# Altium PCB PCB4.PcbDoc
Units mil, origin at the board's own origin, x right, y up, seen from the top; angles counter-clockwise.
Board outline 3880 x 2525 mil, 2 copper layers (Top Layer, Bottom Layer); 34 components, 40 nets, 108 pads, 1 vias.
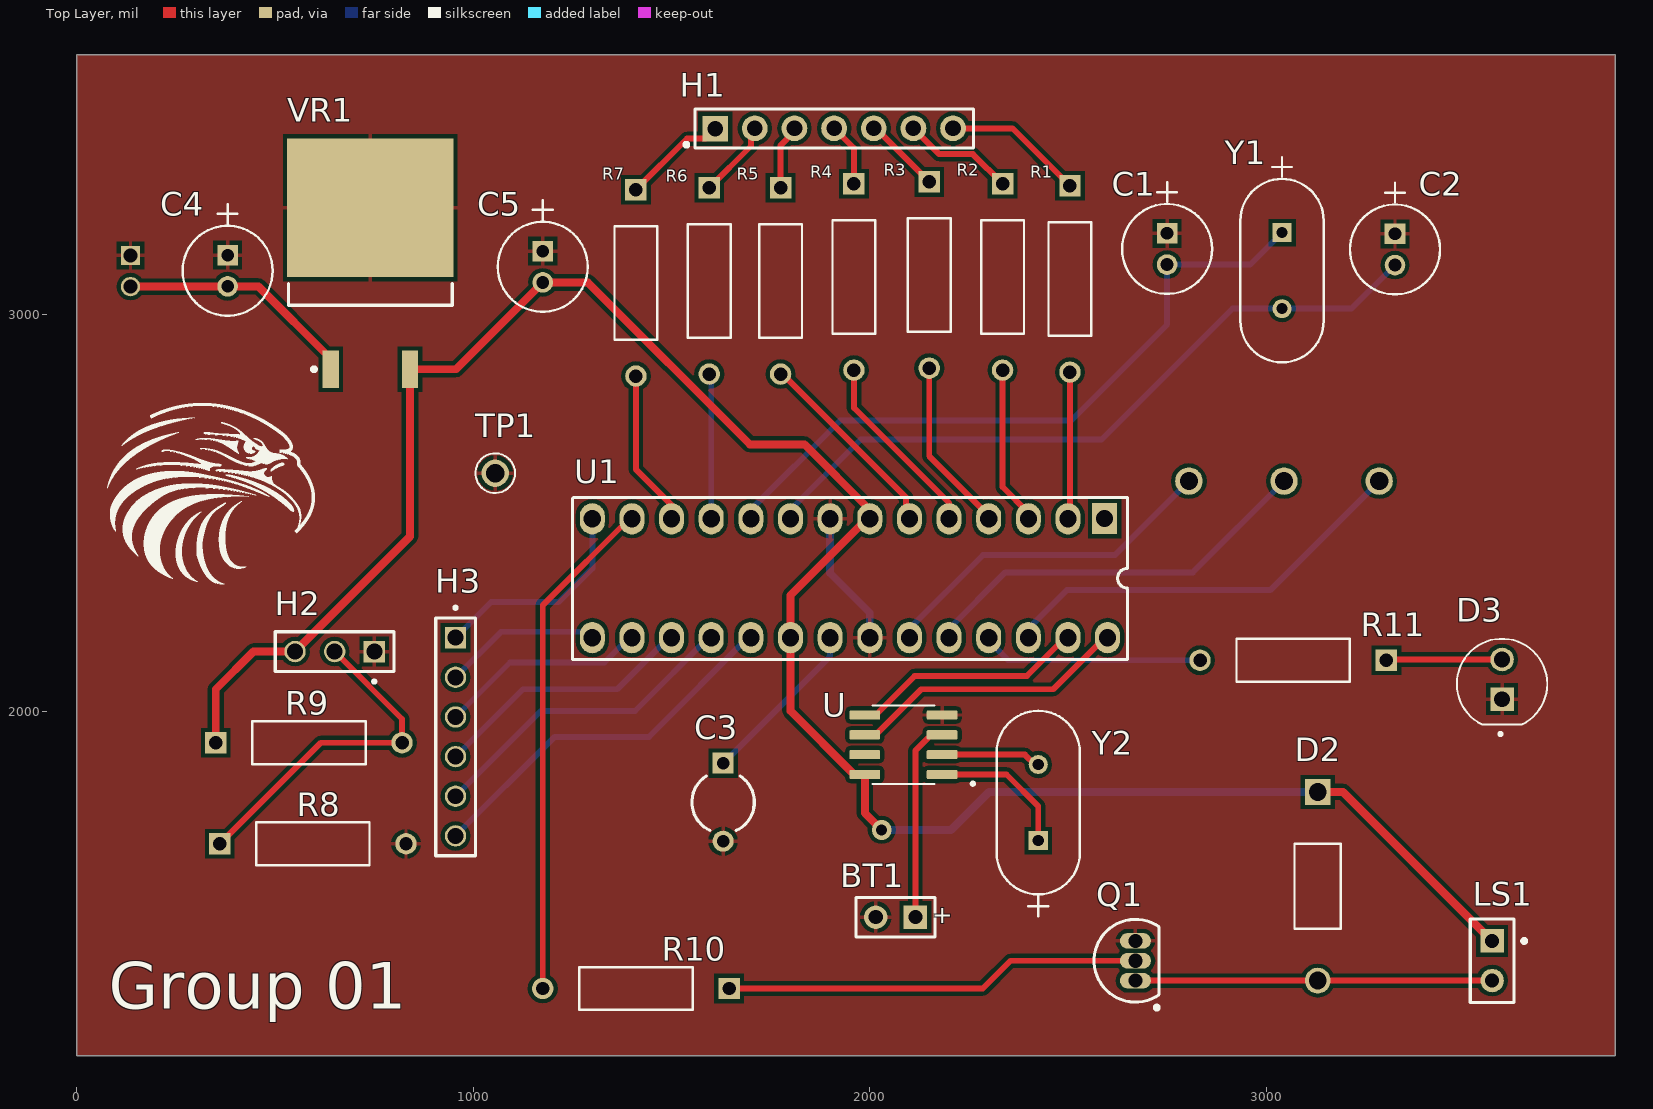
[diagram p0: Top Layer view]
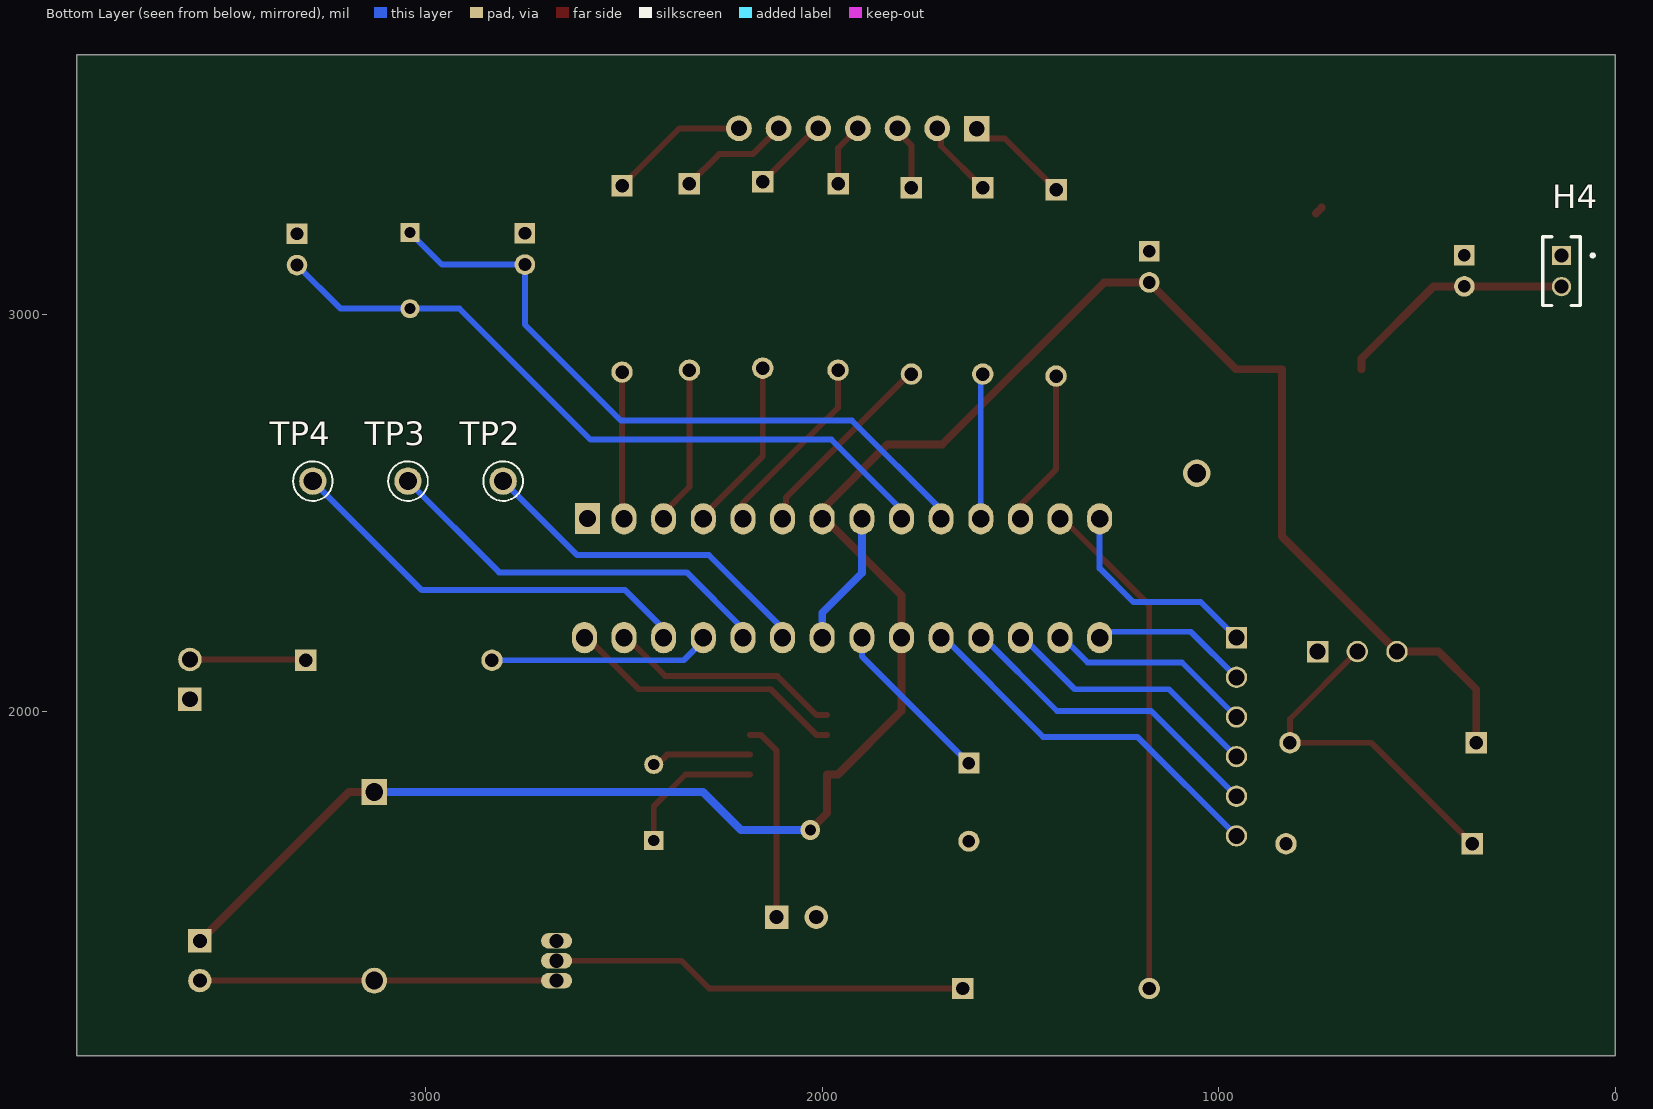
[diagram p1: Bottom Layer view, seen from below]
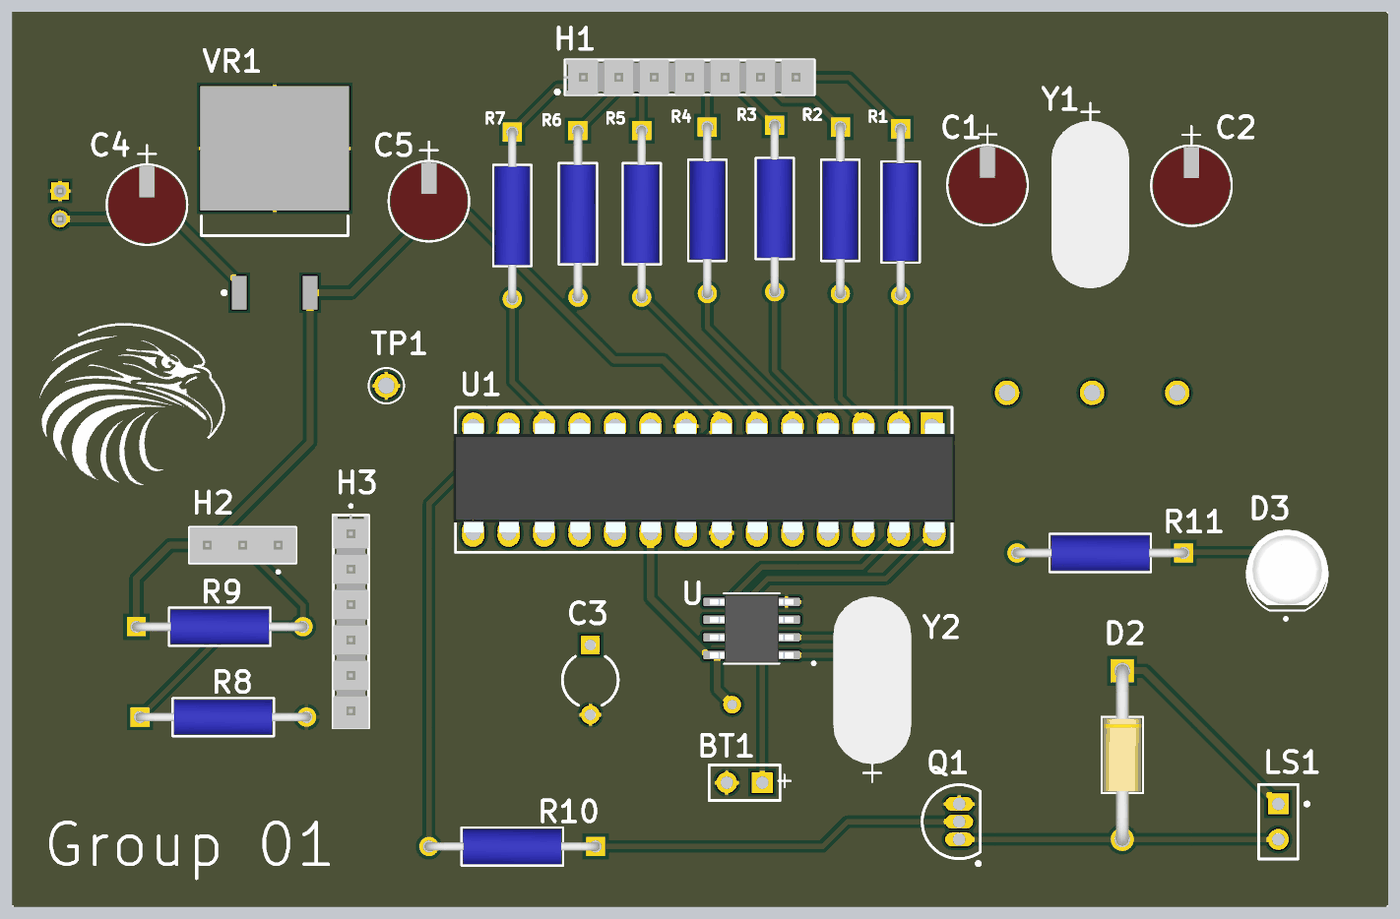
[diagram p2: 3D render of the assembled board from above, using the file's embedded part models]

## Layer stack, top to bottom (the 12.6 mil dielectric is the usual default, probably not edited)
Top Solder: solder mask 0.4, Solder Resist, Dk 3.5
Top Layer: signal copper 1.4
Dielectric 1: dielectric 12.6, FR-4, Dk 4.8
Bottom Layer: signal copper 1.4
Bottom Solder: solder mask 0.4, Solder Resist, Dk 3.5

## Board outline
0,1130 3880,1130 3880,3655 0,3655

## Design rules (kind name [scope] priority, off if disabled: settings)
Clearance [All] p1: gap=10 ignorepadtopadclearanceinfootprint=FALSE except(0: Arc-Hole Track-Hole SMDPad-Hole THPad-Hole Via-Hole Fill-Hole Poly-Hole Region-Hole Text-Hole)
MinimumSolderMaskSliver [All] p1: minsoldermaskwidth=2.6
PolygonConnect [All] p1: connectstyle=Relief reliefconductorwidth=10 reliefentries=4 polygonreliefangle="90 Angle" airgapwidth=10
RoutingVias [All] p1: holewidth=28 width=50 viastyle="Through Hole" minholewidth=28 minwidth=50 maxholewidth=28 maxwidth=50
SilkToSilkClearance [All] p1: silktosilkclearance=7.4
SilkToSolderMaskClearance [IsText] p1: minsilkscreentomaskgap=9.5 clearancetoexposedcopper=TRUE
SolderMaskExpansion [All] p1: expansion=4
Width Width_1 [All] p1: maxlimit=20 minlimit=10 preferedwidth=15 minimp=50.000000 maximp=50.000000 favimp=50.000000
Width [InNet('+5V0') or InNet('GND') or InNet('VCC')] p2: maxlimit=25 minlimit=15 preferedwidth=20 bottomlayer_maxwidth=20 minimp=50.000000 maximp=50.000000 favimp=50.000000
27 further rules are at their usual default settings.

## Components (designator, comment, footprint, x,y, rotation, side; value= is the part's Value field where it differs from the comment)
BT1 "Battery" BAT-2 2065,1480 r180 top
C1 "22pF" CAP_SK100M050ST_CND 2750,3205 r270 top
C2 "22pF" CAP_SK100M050ST_CND 3325,3203.74 r270 top
C3 "Cap2" CAPR5-4X5 1630,1770 r270 top value=100pF
C4 "330pF" CAP_SK100M050ST_CND 380,3150 r270 top
C5 "330pF" CAP_SK100M050ST_CND 1175,3160 r270 top
D2 "1N4001" DO-204AL_VIS 3130,1796 r270 top
D3 "LED" LED_151054RS03000 3595,2080 r90 top
H1 "7x1 Header" TSW-107-XX-XXX-S 1910,3470 r0 top
H2 "3x1 Header" SAMTEC_TSW-101-23-S-T 750,2150 r90 top
H3 "6x1 Header" SAMTEC_TSW-106-05-L-S-LL 955,2185 r270 top
H4 "2x1 Header" SAMTEC_MTMM-101-05-T-D-225 135,3110 r0 bottom
LS1 "Speaker" PIN2 3570,1420 r270 top
Q1 "NPN" TO-226-AA 2670,1370 r0 top
R1 "220Ω" RES_OD_OHM 2505,3325 r270 top
R2 "220Ω" RES_OD_OHM 2335,3330 r270 top
R3 "220Ω" RES_OD_OHM 2150,3335 r270 top
R4 "220Ω" RES_OD_OHM 1960,3330 r270 top
R5 "220Ω" RES_OD_OHM 1775,3320 r270 top
R6 "220Ω" RES_OD_OHM 1595,3320 r270 top
R7 "220Ω" RES_OD_OHM 1410,3315 r270 top
R8 "5KΩ" RES_OD_OHM 360,1665 r0 top
R9 "5KΩ" RES_OD_OHM 350,1920 r0 top
R10 "220Ω" RES_OD_OHM 1645,1300 r180 top
R11 "220Ω" RES_OD_OHM 3303.13,2128.13 r180 top
TP1 "Test Point" KEYSTONE_5000 1055,2600 r0 top
TP2 "Test Point" KEYSTONE_5000 2805,2580 r180 bottom
TP3 "Test Point" KEYSTONE_5000 3045,2580 r180 bottom
TP4 "Test Point" KEYSTONE_5000 3285,2580 r180 bottom
U "DS1307Z+" SOIC127P600X175-8N 2085,1915 r180 top
U1 "ATMEGA328P-PU" 27_DIP_7.62mm 2592.52,2485.39 r270 top
VR1 "Volt Reg" D2PAK_N 740,3130 r90 top
Y1 "XTAL" XTAL_ABL_ABR 3040,3207 r270 top
Y2 "XTAL" XTAL_ABL_ABR 2425,1673 r90 top

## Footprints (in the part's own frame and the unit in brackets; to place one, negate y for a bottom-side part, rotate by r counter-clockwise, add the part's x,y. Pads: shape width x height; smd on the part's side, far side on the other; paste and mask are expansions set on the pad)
27_DIP_7.62mm [mm]
  rect 2x1.6 hole 1.1: 1(0,0)
  oval 2x1.6 hole 1.1: 2(0.01,-2.35) 3(0.01,-4.89) 4(0.01,-7.43) 5(0.01,-9.97) 6(0.01,-12.51) 7(0.01,-15.05) 8(0.01,-17.59) 9(0.01,-20.13) 10(0.01,-22.67) 11(0.01,-25.21) 12(0.01,-27.75) 13(0.01,-30.29) 14(0.01,-32.83) 15(7.63,-32.83) 16(7.63,-30.29) 17(7.63,-27.75) 18(7.63,-25.21) 19(7.63,-22.67) 20(7.63,-20.13) 21(7.63,-17.59) 22(7.63,-15.05) 23(7.63,-12.51) 24(7.63,-9.97) 25(7.63,-7.43) 26(7.63,-4.89) 27(7.63,-2.35) 28(7.63,0.19)
  silkscreen extent -1.35,-34.1 9.02,1.46, body extent -0.23,-34.26 7.65,1.68, height 4.65
BAT-2 [mm] "Battery; 2 Leads"
  rect 1.5x1.5 hole 0.9: 1(-1.27,0)
  round 1.5 hole 0.9: 2(1.27,0)
  silkscreen extent -2.54,-1.27 2.54,1.27
CAP_SK100M050ST_CND [mil]
  rect 52x52 hole 32 mask+0: 1(0,0)
  round 52 hole 32 mask+0: 2(78.74,0)
  silkscreen extent -129,-113 153,114, body extent -70,-108 148,109, height 513
CAPR5-4X5 [mm] "Capacitor; 2 Leads"
  rect 1.35x1.35 hole 0.8: 1(-2.5,0)
  round 1.35 hole 0.8: 2(2.5,0)
  silkscreen extent -1.69,-2 1.82,2
D2PAK_N [mm] "D2-PAK, 4-Leads, Body 8.8x10.4mm, Pitch 2.54mm, Lead Span 15.1mm, IPC Medium Density"
  rect 2.4x1.05 smd: 1(-6.8,2.54) 3(-6.8,-2.54)
  rect 8.9x10.65 smd: 2(3.55,0)
  silkscreen extent -6.92,-5.25 -1.3,5.25, body extent -2.7,-5.28 6.3,5.28, height 4.69
DO-204AL_VIS [mil]
  rect 65x65 hole 45 mask+0: 1(0,0)
  round 65 hole 45 mask+0: 2(476,0)
  silkscreen extent 130,-58 346,59, body extent -17,-54 493,54, height 107
KEYSTONE_5000 [mm]
  round 1.755 hole 1.17: 1(0,0)
  silkscreen extent -1.27,-1.27 1.27,1.27
LED_151054RS03000 [mm]
  round 1.508 hole 1: 1(1.27,0)
  rect 1.508x1.508 hole 1: 2(-1.27,0)
  silkscreen extent -3.6,-2.9 2.6,2.9, body extent -2.51,-2.9 2.9,2.9, height 12.1
PIN2 [mm] "Photosensitive Diode; 2 Leads"
  rect 1.5x1.5 hole 0.9: 1(0,0)
  round 1.5 hole 0.9: 2(2.54,0)
  silkscreen extent -1.4,-1.4 3.94,2.18
RES_OD_OHM [mil]
  rect 54x54 hole 34 mask+0: 1(0,0)
  round 54 hole 34 mask+0: 2(470,0)
  silkscreen extent 92,-54 378,54, body extent -12,-49 482,49, height 98
SAMTEC_MTMM-101-05-T-D-225 [mm]
  rect 1.24x1.24 hole 0.89: 01(0,-1)
  round 1.24 hole 0.89: 02(0,1)
  silkscreen extent -2.1,-2.2 1.2,2.2, body extent -1,-1.97 1,1.97, height 7.21
SAMTEC_TSW-101-23-S-T [mm]
  rect 1.37x1.37 hole 1.02: 01(0,0)
  round 1.37 hole 1.02: 02(0,2.54) 03(0,5.08)
  silkscreen extent -2.02,-1.27 1.27,6.35, body extent -1.27,-1.27 1.27,6.35, height 8.38
SAMTEC_TSW-106-05-L-S-LL [mm]
  rect 1.37x1.37 hole 1.02: 01(0,0)
  round 1.37 hole 1.02: 02(2.54,0) 03(5.08,0) 04(7.62,0) 05(10.16,0) 06(12.7,0)
  silkscreen extent -2.02,-1.27 13.97,1.27, body extent -1.33,-1.27 14.03,1.27, height 5.21
SOIC127P600X175-8N [mm]
  rrect25% 1.97x0.59 smd: 1(-2.475,1.905) 2(-2.475,0.635) 3(-2.475,-0.635) 4(-2.475,-1.905) 5(2.475,-1.905) 6(2.475,-0.635) 7(2.475,0.635) 8(2.475,1.905)
  silkscreen extent -4.54,-2.52 2,2.59, body extent -3,-2.45 3,2.45, height 1.75
TO-226-AA [mm] "TO, Flat Index; 3 In-Line, Axial Leads; Body Dia. 4.8mm; Leads 0.55 x 0.51 mm (max)"
  oval 2x1 hole 0.9: 1(0,-1.27) 2(0,0) 3(0,1.27)
  silkscreen extent -2.65,-3.13 1.52,2.65, body extent -2.65,-2.66 1.52,2.66, height 5.33
TSW-107-XX-XXX-S [mm] "2.54mm pitch, 7 pin, terminal strip; straight, single row"
  rect 1.65x1.65 hole 1 mask+0: 1(-7.62,-0.025)
  round 1.65 hole 1 mask+0: 2(-5.08,0) 3(-2.54,0) 4(0,0) 5(2.54,0) 6(5.08,0) 7(7.62,0)
  silkscreen extent -9.59,-1.25 8.93,1.25, body extent -9.02,-1.27 8.89,1.27, height 18.29
XTAL_ABL_ABR [mil]
  rect 48x48 hole 28 mask+0: 1(0,0)
  round 48 hole 28 mask+0: 2(192,0)
  silkscreen extent -190,-105 328,105, body extent -141,-110 332,110, height 138

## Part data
BT1: "Multicell Battery", Voltage=1.5V
C1 C2 C4 C5: library part SK100M050ST, "No Description Available", Mfr_Name="Cornell Dubilier"
C3: "Capacitor"
D2: library part 1N4001-E3/73, "No Description Available", Mfr_Name=Vishay
D3: library part 151054RS03000, "Red 623nm LED Indication - Discrete 1.9V Radial", Package="Radial Würth Elektronik"
H1: library part Component_1
H2: library part TSW-101-23-S-T, Package=None
H3: library part TSW-106-05-L-S-LL, Package=None
H4: library part MTMM-101-05-T-D-225, "Connector Header Through Hole 2 position", Package=None
LS1: "Loudspeaker"
Q1: "NPN Bipolar Transistor"
R1 R2 R3 R4 R5 R6 R7 R8 R9 R10 R11: library part OD27GJE, "No Description Available", Mfr_Name=Ohmite
TP1 TP2 TP3 TP4: library part 5000, "High Pin Count, Backplane Connectors, Receptacle, Right Angle, Through Hole, 4 Row, 120 Positions, 0 Guide Pin, 2.54mm (0.100in) Pitch", Package="Custom Package Ohmite"
U: "Real Time Clock _RTC_ IC Clock/Calendar 56B I²C, 2-Wire Serial 8-SOIC _0.154, 3.90mm Width_", Package="SO-8 Maxim Integrated"
U1: "ATMEGA328P-PU; 8 bit Microcontroller AVR 20MHz 1; 32kb Flash; 2kb RAM; I2C SPI 2", Case/Package=PDIP, Frequency=20MHz, Manufacturer="Microchip / Atmel", Max Operating Temperature=85°C, Max Supply Voltage=5.5V, Min Operating Temperature=-40°C, Min Supply Voltage=1.8V, Package Quantity=14, Supplier Part Number 1=ATMEGA328P-PU-ND
VR1: "Voltage Regulator"
Y1 Y2: library part ABL-20.000MHZ-B2, "No Description Available", Mfr_Name=Abracon

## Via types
v1: diameter 50, hole 28, Top Layer to Bottom Layer, 1 vias

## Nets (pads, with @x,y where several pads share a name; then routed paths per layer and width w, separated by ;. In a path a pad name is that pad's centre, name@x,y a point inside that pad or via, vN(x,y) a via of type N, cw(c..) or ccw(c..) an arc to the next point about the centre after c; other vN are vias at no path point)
+5V0: C5.2 D2.1 H2.03 LS1.1 R9.1 U1.7 U1.20 U.8 VR1.3 | length 5432.4
  Top Layer w20: R9.1 350,2055 445,2150 H2.03 840,2440 VR1.3 956.02,2862.28 C5.2 1288.74,3081.26 1697.15,2672.85 1835.02,2672.85 2000,2507.87 2000,2492.13 1800,2292.13 U1.20 1800,2000.39 1960.39,1840 U.8 1987.56,1742.44 v1(2030,1700) ; D2.1 3194,1796 LS1.1
  Bottom Layer w20: v1(2030,1700) 2205,1700 2301,1796 D2.1
GND: BT1.2 C1.1 C2.1 C3.2 C4.1 C5.1 D3.2 H2.01 H4.01 Q1.3 R8.2 TP1.1 U1.8 U1.22 U.4 VR1.2 | length 362.6
  Top Layer w20: VR1.2@739.76,3270 VR1.2 VR1.2@754.76,3255
  Bottom Layer w20: U1.8 1900,2347.87 2000,2247.87 U1.22
NetBT1_1: BT1.1 U.3 | length 503.8
  Top Layer w15: BT1.1 2115,1899.73 2155.27,1940 U.3
NetC1_2: C1.2 U1.10 Y1.1 | length 1726.1
  Bottom Layer w15: U1.10@1700,2500 1700,2507.87 1925.07,2732.94 2507.94,2732.94 2750,2975 C1.2 2959.26,3126.26 Y1.1
NetC2_2: C2.2 U1.9 Y1.2 | length 1788.5
  Bottom Layer w15: U1.9@1800,2500 1800,2507.87 1977.13,2685 2585,2685 2915,3015 Y1.2 3215,3015 C2.2
NetC3_1: C3.1 U1.21 | length 428.4
  Bottom Layer w15: C3.1 1900,2138.43 U1.21
NetD2_2: D2.2 LS1.2 Q1.1 | length 900
  Top Layer w15: Q1.1 D2.2 LS1.2
NetD3_1: D3.1 R11.1 | length 292.6
  Top Layer w15: R11.1 3305,2130 D3.1
NetH1_1: H1.1 R7.1 | length 263.8
  Top Layer w15: R7.1 1539.02,3444.02 1585.02,3444.02 H1.1
NetH1_2: H1.2 R6.1 | length 197.6
  Top Layer w15: R6.1 1700.44,3425.44 1700.44,3460.44 H1.2
NetH1_3: H1.3 R5.1 | length 164.5
  Top Layer w15: R5.1 1775,3427.25 1810,3462.25 H1.3
NetH1_4: H1.4 R4.1 | length 160.7
  Top Layer w15: H1.4 1960,3420 R4.1
NetH1_5: H1.5 R3.1 | length 195.9
  Top Layer w15: H1.5 2015,3470 R3.1
NetH1_6: H1.6 R2.1 | length 283
  Top Layer w15: H1.6 2175.03,3404.97 2260.03,3404.97 R2.1
NetH1_7: H1.7 R1.1 | length 355.1
  Top Layer w15: H1.7 2360,3470 R1.1
NetH2_02: H2.02 R8.1 R9.2 | length 866
  Top Layer w15: R8.1 615,1920 R9.2 820,1980 H2.02
NetH3_01: H3.01 U1.14 | length 542.5
  Bottom Layer w15: H3.01 1045,2275 1215,2275 1300,2360 U1.14
NetH3_02: H3.02 U1.15 | length 392.6
  Bottom Layer w15: H3.02 1070,2200 U1.15@1300,2200
NetH3_03: H3.03 U1.16 | length 538.7
  Bottom Layer w15: H3.03 1092.5,2122.5 1330.37,2122.5 1400,2192.13 U1.16@1400,2200
NetH3_04: H3.04 U1.17 | length 680.1
  Bottom Layer w15: H3.04 1125,2055 1362.87,2055 1500,2192.13 U1.17@1500,2200
NetH3_05: H3.05 U1.18 | length 821.5
  Bottom Layer w15: H3.05 1170,2000 1407.87,2000 1600,2192.13 U1.18@1600,2200
NetH3_06: H3.06 U1.19 | length 962.9
  Bottom Layer w15: H3.06 1205,1935 1442.87,1935 1700,2192.13 U1.19@1700,2200
NetQ1_2: Q1.2 R10.1 | length 1054
  Top Layer w15: R10.1 2285,1300 2355,1370 Q1.2
NetR1_2: R1.2 U1.2 | length 357.1
  Top Layer w15: U1.2@2500,2500 2500,2507.87 2505,2512.87 R1.2
NetR2_2: R2.2 U1.3 | length 386.9
  Top Layer w15: R2.2 2335,2565 U1.3@2400,2500
NetR3_2: R3.2 U1.4 | length 442.1
  Top Layer w15: R3.2 2150,2642.87 2300,2492.87 U1.4
NetR4_2: R4.2 U1.5 | length 459.4
  Top Layer w15: R4.2 1960,2765 2200,2525 U1.5@2200,2500
NetR5_2: R5.2 U1.6 | length 487.5
  Top Layer w15: R5.2 1780,2850 2091.77,2538.23 2091.77,2508.23 U1.6@2100,2500
NetR6_2: R6.2 U1.11 | length 352.1
  Bottom Layer w15: R6.2 1600,2845 U1.11@1600,2500
NetR7_2: R7.2 U1.12 | length 382.3
  Top Layer w15: R7.2 1410,2609.51 1500,2519.51 U1.12@1500,2500
NetR10_2: R10.2 U1.13 | length 1293.2
  Top Layer w15: R10.2 1175,2267.13 1400,2492.13 U1.13@1400,2500
NetR11_2: R11.2 U1.25 | length 561.3
  Bottom Layer w15: U1.25 2300,2177.13 2349,2128.13 R11.2
NetTP2_1: TP2.1 U1.23 | length 867
  Bottom Layer w15: U1.23@2100,2200 2100,2207.87 2285.48,2393.35 2618.35,2393.35 TP2.1
NetTP3_1: TP3.1 U1.24 | length 1007
  Bottom Layer w15: U1.24@2200,2200 2200,2207.87 2342.13,2350 2815,2350 TP3.1
NetTP4_1: TP4.1 U1.26 | length 1047
  Bottom Layer w15: U1.26@2400,2200 2400,2207.87 2497.13,2305 3010,2305 TP4.1
NetU1_27: U1.27 U.5 | length 604
  Top Layer w15: U.5 2014.73,1990 2113.25,2088.53 2396.4,2088.53 2500,2192.13 U1.27@2500,2200
NetU1_28: U1.28 U.6 | length 724.7
  Top Layer w15: U.6 2014.73,1940 2129.73,2055 2462.87,2055 2600,2192.13 U1.28@2600,2200
NetU_1: U.1 Y2.1 | length 362.7
  Top Layer w15: U.1 2345,1840 2425,1760 Y2.1
NetU_2: U.2 Y2.2 | length 252.9
  Top Layer w15: U.2 2391.07,1890 2416.07,1865 Y2.2
VCC: C4.2 H4.02 VR1.1 | length 607.4
  Top Layer w20: H4.02 379.37,3070.63 C4.2 457.6,3071.26 640,2888.86 VR1.1
pads on no net: U1.1 U.7

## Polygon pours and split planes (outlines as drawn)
GND on Top Layer "Top Layer-GND" (solid, pour order 0): 0,1130 0,3655 3880,3655 3880,1130

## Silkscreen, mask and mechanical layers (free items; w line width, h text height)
Top Overlay:
  drawing of 14 lines, arcs and shapes, not listed
  text "Group 01" at 80,1249.36 h118.11

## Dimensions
0,1130 to 3880,1130 on Top Overlay
3880,3655 to 3880,1130 on Top Overlay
